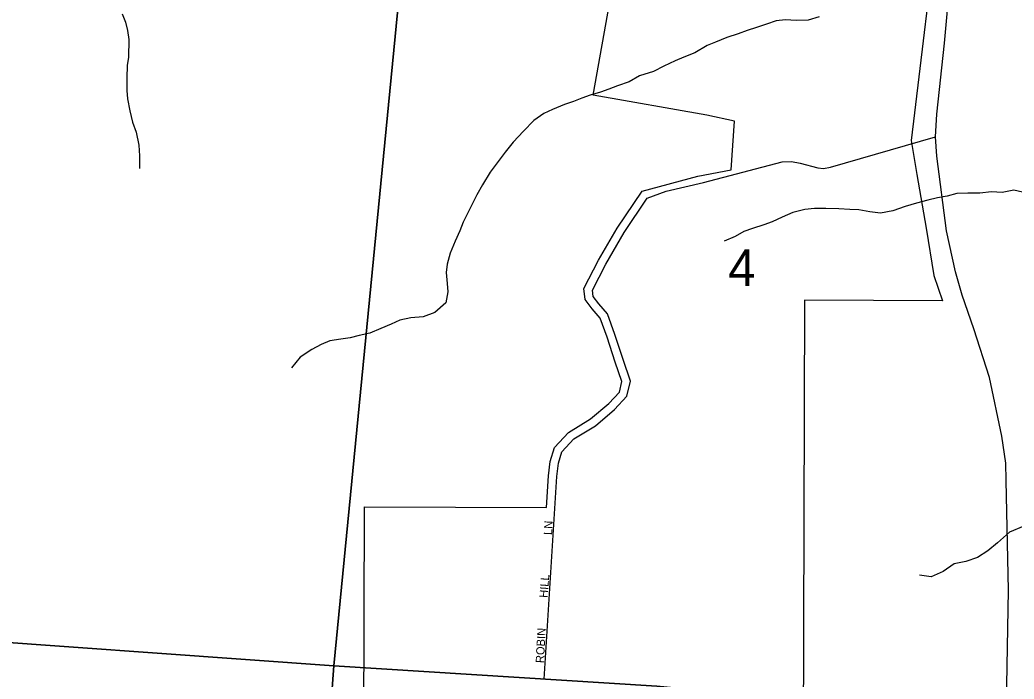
# Model space of a CAD drawing. Extents: x 1715311 to 2083412, y 146837 to 553079.
# Drawn here: x 1929182 to 1935157, y 368291 to 372254 of the extents above; entities that cross this region are included whole.
import ezdxf

# ---------------------------------------------------------------- set-up
doc = ezdxf.new("R2010")
doc.units = 0
for name, color, linetype in [('GM_X_City_Street', 7, 'Continuous'), ('GM_X_City_Street_Text', 7, 'Continuous'), ('GM_X_Corporation', 7, 'Continuous'), ('GM_X_County_Road', 7, 'Continuous'), ('GM_X_Minor_River', 7, 'Continuous'), ('GM_X_Section', 7, 'Continuous'), ('GM_X_Section_Text', 7, 'Continuous')]:
    doc.layers.add(name, color=color, linetype=linetype)

msp = doc.modelspace()

# ---------------------------------------------------------------- linework, layer by layer
at = {"layer": 'GM_X_City_Street'}
msp.add_lwpolyline([(1932332.4, 368291), (1932408, 369508.8), (1932418.4, 369588.9), (1932438.7, 369656.9), (1932511.1, 369734.7), (1932641.5, 369814.3), (1932756, 369911.9), (1932830.4, 369991.7), (1932850.8, 370081.8), (1932807.4, 370212.2), (1932758.1, 370362.7), (1932712.6, 370487.2), (1932660.9, 370547.5), (1932627.1, 370591.7), (1932623.3, 370629.8), (1932704, 370785.7), (1932812.9, 370975.5), (1932951.9, 371181.3), (1933066.5, 371225.1), (1933289.7, 371275.4), (1933762.2, 371400.1), (1933819.9, 371401.9), (1933872, 371392.7), (1933978, 371364.7), (1934011.5, 371361), (1934054.2, 371368.5), (1934684.9, 371550.8)], dxfattribs=at)
at = {"layer": 'GM_X_Corporation'}
for points in [[(1931248.9, 368006.4), (1931253.2, 369326.5), (1932346.4, 369323), (1932358.2, 369513.6), (1932369.3, 369599.3), (1932394.1, 369682.4), (1932479.2, 369773.8), (1932612.1, 369854.9), (1932721.4, 369948.1), (1932784.6, 370015.9), (1932799, 370079.2), (1932759.9, 370196.5), (1932710.8, 370346.3), (1932668.8, 370461.5), (1932622, 370516), (1932578.8, 370572.6), (1932572, 370639.6), (1932660.1, 370809.7), (1932770.5, 371002), (1932920.9, 371224.7), (1933255.4, 371314.8), (1933456.5, 371352.1), (1933477.4, 371644.5), (1933310.2, 371680.3), (1932627.8, 371801.6), (1932940.7, 373562.5)], [(1934708.4, 372945.2), (1934539.1, 371529.5), (1934573.2, 371325.1), (1934628.8, 371002.7), (1934673.9, 370716.9), (1934726.5, 370565.4), (1933897.1, 370568.1), (1933884.4, 366607.6)]]:
    msp.add_lwpolyline(points, dxfattribs=at)
at = {"layer": 'GM_X_County_Road'}
msp.add_lwpolyline([(1934840.3, 365923), (1934840.3, 365923), (1934895.7, 366213.4), (1934955.5, 366767), (1935067.3, 367543.2), (1935088.4, 367796.8), (1935095.4, 367863.8), (1935109.5, 368025.8), (1935123.6, 368825.4), (1935109.8, 369485.3), (1935106.9, 369589.8), (1935083.7, 369752.3), (1935008.2, 370103.6), (1934915.4, 370396.7), (1934845.7, 370598.2), (1934804.1, 370738.9), (1934750.3, 370985.5), (1934692.5, 371435.5), (1934684.9, 371550.8), (1934692.5, 371687.7), (1934739.2, 372114.7), (1934769.8, 372470.5), (1934780.7, 372807.5), (1934778.4, 372912.2)], dxfattribs=at)
at = {"layer": 'GM_X_Minor_River'}
for points in [[(1929796.9, 372290.9), (1929816.5, 372240.7), (1929828.2, 372190.6), (1929835.8, 372136.5), (1929835.1, 372030.3), (1929826.7, 371980.3), (1929824.2, 371906.3), (1929823.7, 371830.2), (1929829.4, 371780.1), (1929842.8, 371707.9), (1929858.4, 371639.7), (1929879.9, 371579.5), (1929897.4, 371501.2), (1929900.9, 371437.2), (1929900.4, 371361.1)], [(1933986, 372271.4), (1933920, 372251.6), (1933848, 372249.8), (1933782.1, 372254.1), (1933726.1, 372248.3), (1933668.1, 372228.4), (1933608.1, 372208.6), (1933552.1, 372190.8), (1933498, 372170.9), (1933430, 372147.1), (1933362, 372119.3), (1933312, 372099.5), (1933237.9, 372055.7), (1933171.8, 372029.9), (1933119.8, 372008), (1933051.8, 371976.2), (1932990.5, 371943.2)], [(1932990.5, 371943.2), (1932905.1, 371917.7), (1932843, 371882), (1932772.9, 371856.5), (1932720.8, 371836.8), (1932670.7, 371819.1), (1932608.7, 371801.5), (1932558.6, 371783.8), (1932508.5, 371764.1), (1932454.4, 371744.5), (1932382.3, 371714.9), (1932330.2, 371691.2), (1932270, 371649.6), (1932207.6, 371583.9), (1932147.2, 371518.2), (1932098.8, 371458.5), (1932008.1, 371338.9), (1931961.6, 371263.1), (1931927.3, 371201.3), (1931900.9, 371145.4), (1931846.2, 371037.6), (1931825.9, 370985.7), (1931797.5, 370923.8), (1931767, 370851.9), (1931750.6, 370786), (1931744.3, 370736), (1931749.8, 370669.8), (1931753.5, 370619.7), (1931741, 370553.8), (1931674.7, 370494.1), (1931604.6, 370468.5), (1931530.6, 370463), (1931464.6, 370449.5), (1931412.5, 370423.8), (1931350.4, 370398.2), (1931284.3, 370370.6), (1931220.2, 370357), (1931166.2, 370343.3), (1931110.2, 370333.7), (1931044.2, 370324.1), (1930992.1, 370302.4), (1930936, 370272.8), (1930865.7, 370227.2), (1930813.3, 370161.5)], [(1935207.3, 371218), (1935155.4, 371230.2), (1935085.4, 371216.5), (1935021.5, 371220.7), (1934951.5, 371212.9), (1934879.5, 371211.1), (1934813.6, 371209.4), (1934755.6, 371193.5), (1934695.6, 371183.7), (1934637.6, 371169.9), (1934569.6, 371152.1), (1934501.6, 371132.3), (1934427.6, 371106.5), (1934353.6, 371092.8), (1934289.7, 371099), (1934223.8, 371111.2), (1934169.8, 371113.4), (1934103.9, 371117.7), (1934026, 371119.9), (1933958, 371120.2), (1933900.1, 371114.3), (1933828.1, 371096.6), (1933764, 371068.8), (1933702, 371038.9), (1933652, 371021.1), (1933583.9, 370999.3), (1933531.9, 370981.4), (1933479.9, 370951.6), (1933413.8, 370923.8)], [(1935214.4, 369209.7), (1935128.3, 369173.9), (1935056.2, 369110.1), (1934998.1, 369062.2), (1934936, 369022.4), (1934866, 368998.6), (1934796, 368984.8), (1934729.9, 368937), (1934657.8, 368905.2), (1934587.9, 368915.5)]]:
    msp.add_lwpolyline(points, dxfattribs=at)
at = {"layer": 'GM_X_Section'}
for points in [[(1926539.2, 374077.9), (1931589, 373719.5), (1931067.9, 368370), (1925814.1, 368746.8), (1926287.1, 374098.4)], [(1932139, 373684.4), (1936715.6, 373285.2), (1936391.8, 367922.8), (1933009.6, 368248), (1931067.9, 368370), (1931589, 373719.5)], [(1925814.1, 368746.8), (1931067.9, 368370), (1930675.8, 363042.2), (1925372, 363464.9)], [(1931067.9, 368370), (1933009.6, 368248), (1936391.8, 367922.8), (1936211.1, 362598.5), (1930989.8, 363013.6), (1930675.8, 363042.2)]]:
    msp.add_lwpolyline(points, close=True, dxfattribs=at)

# ---------------------------------------------------------------- texts
at = {"layer": 'GM_X_City_Street_Text'}
for s, rotation, p in [('LN', 86.97755, (1932380.1, 369156.3)), ('HILL', 85.9166, (1932353.7, 368778.1)), ('ROBIN', 87.33841, (1932331.6, 368386.3))]:
    msp.add_text(s, height=50, rotation=rotation, dxfattribs=at).set_placement(p)
at = {"layer": 'GM_X_Section_Text'}
msp.add_text('4', height=221, rotation=0.00001, dxfattribs=at).set_placement((1933438.8, 370653.8))

doc.saveas('drawing.dxf')
